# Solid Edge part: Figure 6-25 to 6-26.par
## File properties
Author: CADCIM
Template: Normal.par
Last saved by: TIET
Revision: 4
Application: Solid Edge
Accuracy: 0.99
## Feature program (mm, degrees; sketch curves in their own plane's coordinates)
sketch for "unnamed Protrusion 1" plane through (0, 0, 0) normal (0, -1, 0) x-axis (1, 0, 0)
  line (-47.9688, 46.8859) -> (-47.9688, 0)
  line (-47.9688, 0) -> (40.7735, 0)
  line (40.7735, 0) -> (-11.0972, 46.8859)
  line (-11.0972, 46.8859) -> (-47.9688, 46.8859)
extrude "unnamed Protrusion 1" add finite 57.15 symmetric
sketch for "ExtrudedProtrusion_3" plane through (16.4336, 0, 22.0008) normal (0.670562, 0, 0.741854) x-axis (0, 1, 0)
  circle centre (0, 0.7308) radius 21.6522
extrude "ExtrudedProtrusion_3" add finite 41.275 along +normal
fillet "Round_6" radius 20
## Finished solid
Body 1: solid body, 12 faces, 26 edges, 16 vertices.
  Faces by surface: plane 10, cylinder 1, torus 1
  Edges by curve: line 16, circle 6, intersection 4
Bounding box of the edges (mm; curved faces can reach further): 107.600 x 57.150 x 67.630, from (-47.9688, -28.575, 0) to (59.6317, 28.575, 67.63).
Cylindrical faces by radius (mm): R21.6522 x1
Toroidal faces (ring radius, tube radius in mm): R41.6522 r20 x1
Planar faces by outward normal: +y 1, +z 1, -x 1, -y 1, -z 1, oblique 5
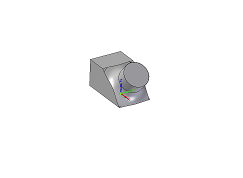
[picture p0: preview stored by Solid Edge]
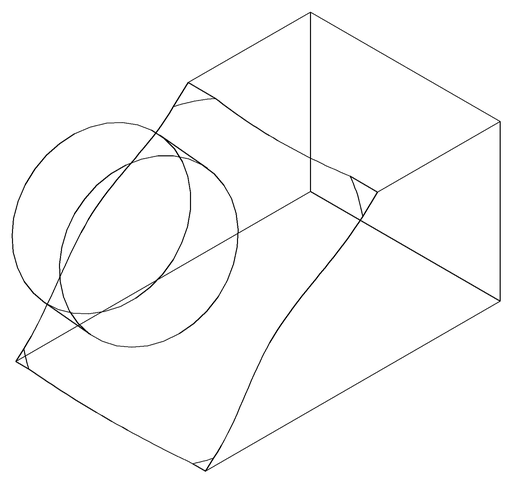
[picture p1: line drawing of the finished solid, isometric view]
